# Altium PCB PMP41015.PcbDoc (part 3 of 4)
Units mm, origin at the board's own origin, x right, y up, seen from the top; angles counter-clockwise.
Board outline 173 x 85 mm, 2 copper layers (Top Layer, Bottom Layer), stack 1.575 mm thick; 89 components, 48 nets, 216 pads, 3458 vias.
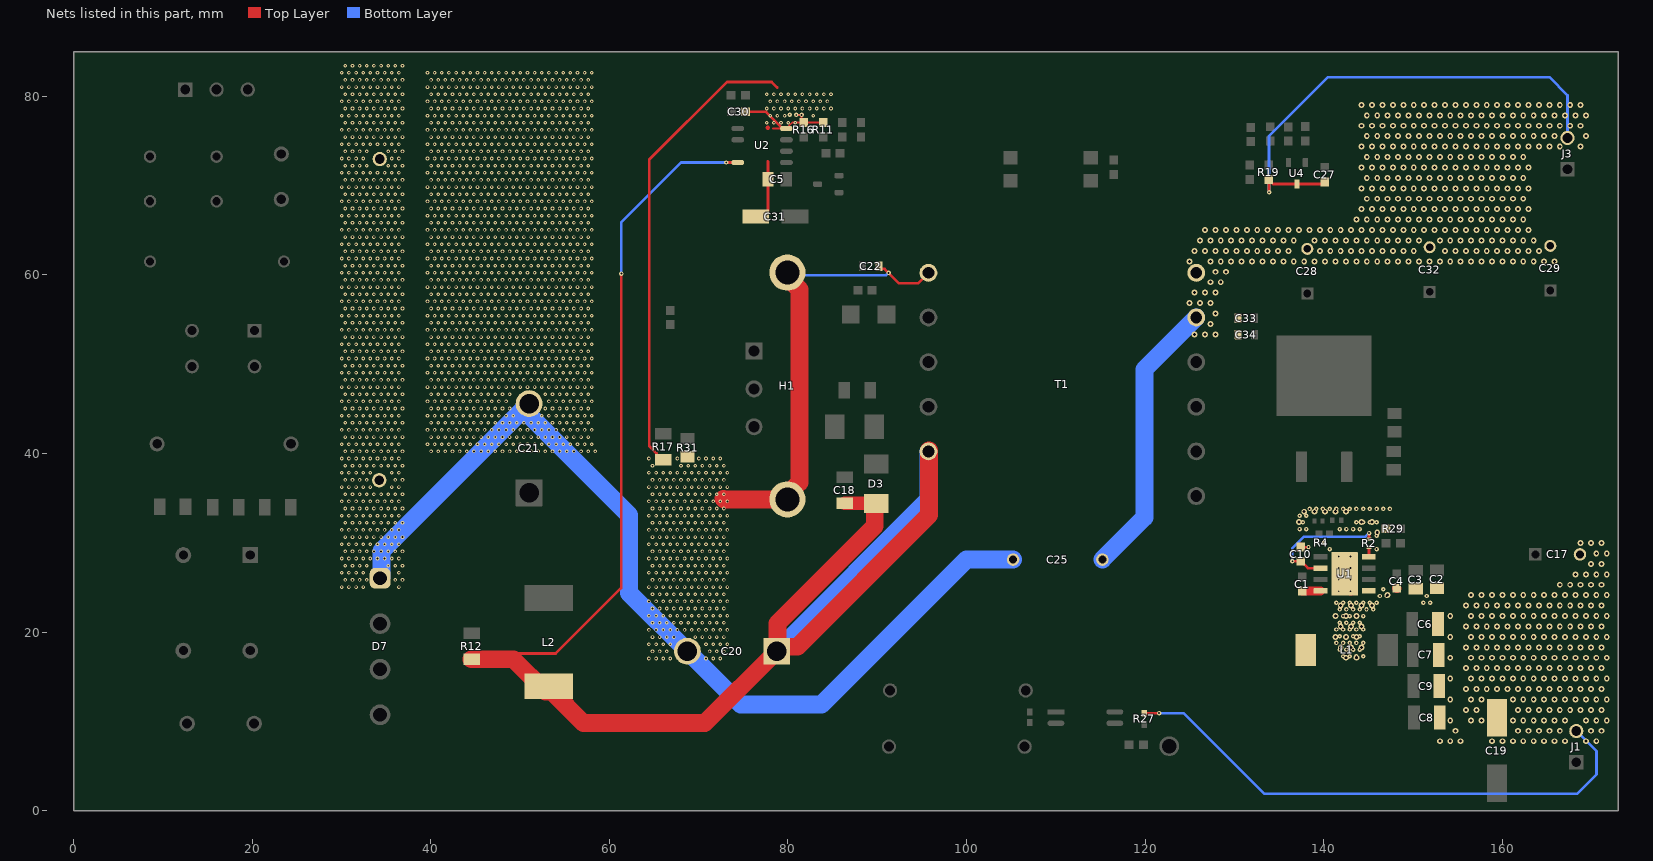
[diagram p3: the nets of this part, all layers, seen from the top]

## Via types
v1: diameter 0.4, hole 0.2, Top Layer to Bottom Layer, 2240 vias
v2: diameter 0.66, hole 0.33, Top Layer to Bottom Layer, 1066 vias
v3: diameter 0.5, hole 0.2, Top Layer to Bottom Layer, 105 vias
v4: diameter 0.67, hole 0.33, Top Layer to Bottom Layer, tented both sides, 41 vias
v5: diameter 0.5, hole 0.2, Top Layer to Bottom Layer, tented both sides, 4 vias
v6: diameter 0.61, hole 0.203, Top Layer to Bottom Layer, tented both sides, 2 vias

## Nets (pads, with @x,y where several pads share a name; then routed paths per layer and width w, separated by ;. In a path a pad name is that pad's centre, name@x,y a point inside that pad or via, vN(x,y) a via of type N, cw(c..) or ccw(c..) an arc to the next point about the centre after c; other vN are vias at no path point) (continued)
PGND: C5.2 C20.2 C21.2 C22.1 C25.1 C30.2 C31.2 D7.1 H1.1 H1.2 pad.1 R11.1 R16.1 R17.1 R31.1 T1.1 U2.4 | length 232
  Top Layer w0.2: 78.338,76.4 79.4,76.4 U2.4@79.825,76.4 80.495,77.07 R16.1@81.754,77.07 ; v3(80.937,77.925) v3(81.521,77.925) ; v3@81.648,78.052 v3(81.521,77.925) ; R16.1@82.08,77.354 R16.1@81.796,77.07 ; R11.1@83.964,77.07 R16.1@81.796,77.07 ; v3(81.521,77.925) 81.521,77.303 R16.1@81.754,77.07 ; R16.1@81.754,77.07 R16.1@81.796,77.07 ; R16.1@81.754,77.07 R16.1@81.775,77.049 R16.1@81.796,77.07
  Top Layer w0.3: R17.1@66.048,39.317 65.773,39.317 65.273,39.817 65.273,40.008 64.463,40.818 64.463,72.907 73.165,81.608 78.181,81.608 78.791,80.999 ; C30.2@75.264,78.27 77.53,78.27 U2.4@79.4,76.4 ; C31.2@76.403,66.541 77.103,66.541 77.758,67.195 C5.2@77.758,70.726 77.758,72.688 77.748,72.698 ; C22.1@90.215,60.96 90.215,60.929 90.465,60.679 90.807,60.679 v3(91.262,60.223) 92.431,59.055 94.554,59.055 T1.1@95.733,60.234
  Top Layer w0.5: 77.748,76.488 77.762,76.503
  Top Layer w2: 72.798,34.929 72.865,34.862 H1.2@79.93,34.862 79.93,35.417 81.28,36.767 81.28,58.357 79.93,59.708 H1.1@79.93,60.262
  Bottom Layer w0.3: H1.2@79.93,34.862 H1.2@79.93,34.878 ; H1.1@79.93,60.262 80.223,59.969 90.986,59.969 91.24,60.223 v3(91.262,60.223)
  Bottom Layer w2: D7.1@34.32,26.033 34.482,26.196 34.482,29.065 C21.2@51.003,45.585 51.003,44.298 62.205,33.096 62.205,24.388 C20.2@68.736,17.856 74.705,11.887 83.769,11.887 100,28.118 C25.1@105.211,28.118
  other v1: 64.423,17.036 65.223,17.036 66.023,17.036 66.823,17.036 70.823,17.036 71.623,17.036 72.423,17.036 64.823,17.836 65.623,17.836 66.423,17.836 71.223,17.836 72.023,17.836 72.823,17.836 64.423,18.636 65.223,18.636 66.023,18.636 66.823,18.636 70.823,18.636 71.623,18.636 72.423,18.636 73.223,18.636 64.823,19.436 65.623,19.436 66.423,19.436 67.223,19.436 69.623,19.436 70.423,19.436 71.223,19.436 72.023,19.436 72.823,19.436 64.423,20.236 65.223,20.236 66.023,20.236 66.823,20.236 67.623,20.236 68.423,20.236 69.223,20.236 70.023,20.236 70.823,20.236 71.623,20.236 72.423,20.236 73.223,20.236 64.823,21.036 65.623,21.036 66.423,21.036 67.223,21.036 68.023,21.036 68.823,21.036 69.623,21.036 70.423,21.036 71.223,21.036 72.023,21.036 72.823,21.036 64.423,21.836 65.223,21.836 66.023,21.836 66.823,21.836 67.623,21.836 68.423,21.836 69.223,21.836 70.023,21.836 70.823,21.836 71.623,21.836 72.423,21.836 73.223,21.836 64.823,22.636 65.623,22.636 66.423,22.636 67.223,22.636 68.023,22.636 68.823,22.636 69.623,22.636 70.423,22.636 71.223,22.636 72.023,22.636 72.823,22.636 64.423,23.436 65.223,23.436 66.023,23.436 66.823,23.436 67.623,23.436 68.423,23.436 69.223,23.436 70.023,23.436 70.823,23.436 71.623,23.436 72.423,23.436 73.223,23.436 64.823,24.236 65.623,24.236 66.423,24.236 67.223,24.236 68.023,24.236 68.823,24.236 69.623,24.236 70.423,24.236 71.223,24.236 72.023,24.236 72.823,24.236 30.023,25.036 30.823,25.036 31.623,25.036 32.423,25.036 36.423,25.036 64.423,25.036 65.223,25.036 66.023,25.036 66.823,25.036 67.623,25.036 68.423,25.036 69.223,25.036 70.023,25.036 70.823,25.036 71.623,25.036 72.423,25.036 73.223,25.036 30.423,25.836 31.223,25.836 32.023,25.836 32.823,25.836 36.023,25.836 36.823,25.836 64.823,25.836 65.623,25.836 66.423,25.836 67.223,25.836 68.023,25.836 68.823,25.836 69.623,25.836 70.423,25.836 71.223,25.836 72.023,25.836 72.823,25.836 30.023,26.636 30.823,26.636 31.623,26.636 32.423,26.636 36.423,26.636 64.423,26.636 65.223,26.636 66.023,26.636 66.823,26.636 67.623,26.636 68.423,26.636 69.223,26.636 70.023,26.636 70.823,26.636 71.623,26.636 72.423,26.636 73.223,26.636 30.423,27.436 31.223,27.436 32.023,27.436 32.823,27.436 35.223,27.436 36.023,27.436 36.823,27.436 64.823,27.436 65.623,27.436 66.423,27.436 67.223,27.436 68.023,27.436 68.823,27.436 69.623,27.436 70.423,27.436 71.223,27.436 72.023,27.436 72.823,27.436 30.023,28.236 30.823,28.236 31.623,28.236 32.423,28.236 33.223,28.236 34.023,28.236 34.823,28.236 35.623,28.236 36.423,28.236 64.423,28.236 65.223,28.236 66.023,28.236 66.823,28.236 67.623,28.236 68.423,28.236 69.223,28.236 70.023,28.236 70.823,28.236 71.623,28.236 72.423,28.236 73.223,28.236 30.423,29.036 31.223,29.036 32.023,29.036 32.823,29.036 33.623,29.036 34.423,29.036 35.223,29.036 36.023,29.036 36.823,29.036 64.823,29.036 65.623,29.036 66.423,29.036 67.223,29.036 68.023,29.036 68.823,29.036 69.623,29.036 70.423,29.036 71.223,29.036 72.023,29.036 72.823,29.036 30.023,29.836 30.823,29.836 31.623,29.836 32.423,29.836 33.223,29.836 34.023,29.836 34.823,29.836 35.623,29.836 36.423,29.836 64.423,29.836 65.223,29.836 66.023,29.836 66.823,29.836 67.623,29.836 68.423,29.836 69.223,29.836 70.023,29.836 70.823,29.836 71.623,29.836 72.423,29.836 73.223,29.836 30.423,30.636 31.223,30.636 32.023,30.636 32.823,30.636 33.623,30.636 34.423,30.636 35.223,30.636 36.023,30.636 36.823,30.636 64.823,30.636 65.623,30.636 66.423,30.636 67.223,30.636 68.023,30.636 68.823,30.636 69.623,30.636 70.423,30.636 71.223,30.636 72.023,30.636 72.823,30.636 30.023,31.436 30.823,31.436 31.623,31.436 32.423,31.436 33.223,31.436 34.023,31.436 34.823,31.436 35.623,31.436 36.423,31.436 64.423,31.436 65.223,31.436 66.023,31.436 66.823,31.436 67.623,31.436 68.423,31.436 69.223,31.436 70.023,31.436 70.823,31.436 71.623,31.436 72.423,31.436 73.223,31.436 30.423,32.236 31.223,32.236 32.023,32.236 32.823,32.236 33.623,32.236 34.423,32.236 35.223,32.236 36.023,32.236 36.823,32.236 64.823,32.236 65.623,32.236 66.423,32.236 67.223,32.236 68.023,32.236 68.823,32.236 69.623,32.236 70.423,32.236 71.223,32.236 72.023,32.236 72.823,32.236 30.023,33.036 30.823,33.036 31.623,33.036 32.423,33.036 33.223,33.036 34.023,33.036 34.823,33.036 35.623,33.036 36.423,33.036 64.423,33.036 65.223,33.036 66.023,33.036 66.823,33.036 67.623,33.036 68.423,33.036 69.223,33.036 70.023,33.036 70.823,33.036 71.623,33.036 72.423,33.036 73.223,33.036 30.423,33.836 31.223,33.836 32.023,33.836 32.823,33.836 33.623,33.836 34.423,33.836 35.223,33.836 36.023,33.836 36.823,33.836 64.823,33.836 65.623,33.836 66.423,33.836 67.223,33.836 68.023,33.836 68.823,33.836 69.623,33.836 70.423,33.836 71.223,33.836 72.023,33.836 72.823,33.836 30.023,34.636 30.823,34.636 31.623,34.636 32.423,34.636 33.223,34.636 34.023,34.636 34.823,34.636 35.623,34.636 36.423,34.636 64.423,34.636 65.223,34.636 66.023,34.636 66.823,34.636 67.623,34.636 68.423,34.636 69.223,34.636 70.023,34.636 70.823,34.636 71.623,34.636 72.423,34.636 73.223,34.636 30.423,35.436 31.223,35.436 32.023,35.436 32.823,35.436 33.623,35.436 34.423,35.436 35.223,35.436 36.023,35.436 36.823,35.436 64.823,35.436 65.623,35.436 66.423,35.436 67.223,35.436 68.023,35.436 68.823,35.436 69.623,35.436 70.423,35.436 71.223,35.436 72.023,35.436 72.823,35.436 30.023,36.236 30.823,36.236 31.623,36.236 32.423,36.236 33.223,36.236 35.623,36.236 36.423,36.236 64.423,36.236 65.223,36.236 66.023,36.236 66.823,36.236 67.623,36.236 68.423,36.236 69.223,36.236 70.023,36.236 70.823,36.236 71.623,36.236 72.423,36.236 73.223,36.236 30.423,37.036 31.223,37.036 32.023,37.036 32.823,37.036 36.023,37.036 36.823,37.036 64.823,37.036 65.623,37.036 66.423,37.036 67.223,37.036 68.023,37.036 68.823,37.036 69.623,37.036 70.423,37.036 71.223,37.036 72.023,37.036 72.823,37.036 30.023,37.836 30.823,37.836 31.623,37.836 32.423,37.836 33.223,37.836 35.623,37.836 36.423,37.836 64.423,37.836 65.223,37.836 66.023,37.836 66.823,37.836 67.623,37.836 68.423,37.836 69.223,37.836 70.023,37.836 70.823,37.836 71.623,37.836 72.423,37.836 73.223,37.836 30.423,38.636 31.223,38.636 32.023,38.636 32.823,38.636 33.623,38.636 34.423,38.636 35.223,38.636 36.023,38.636 36.823,38.636 64.823,38.636 68.023,38.636 68.823,38.636 69.623,38.636 70.423,38.636 71.223,38.636 72.023,38.636 72.823,38.636 30.023,39.436 30.823,39.436 31.623,39.436 32.423,39.436 33.223,39.436 34.023,39.436 34.823,39.436 35.623,39.436 36.423,39.436 64.423,39.436 67.623,39.436 70.023,39.436 70.823,39.436 71.623,39.436 72.423,39.436 30.423,40.236 31.223,40.236 32.023,40.236 32.823,40.236 33.623,40.236 34.423,40.236 35.223,40.236 36.023,40.236 36.823,40.236 40.023,40.236 40.823,40.236 41.623,40.236 42.423,40.236 43.223,40.236 44.023,40.236 44.823,40.236 45.623,40.236 46.423,40.236 47.223,40.236 48.023,40.236 48.823,40.236 49.623,40.236 50.423,40.236 51.223,40.236 52.023,40.236 52.823,40.236 53.623,40.236 54.423,40.236 55.223,40.236 56.023,40.236 56.823,40.236 57.623,40.236 58.423,40.236 30.023,41.036 30.823,41.036 31.623,41.036 32.423,41.036 33.223,41.036 34.023,41.036 34.823,41.036 35.623,41.036 36.423,41.036 39.623,41.036 40.423,41.036 41.223,41.036 42.023,41.036 42.823,41.036 43.623,41.036 44.423,41.036 45.223,41.036 46.023,41.036 46.823,41.036 47.623,41.036 48.423,41.036 49.223,41.036 50.023,41.036 50.823,41.036 51.623,41.036 52.423,41.036 53.223,41.036 54.023,41.036 54.823,41.036 55.623,41.036 56.423,41.036 57.223,41.036 58.023,41.036 30.423,41.836 31.223,41.836 32.023,41.836 32.823,41.836 33.623,41.836 34.423,41.836 35.223,41.836 36.023,41.836 36.823,41.836 40.023,41.836 40.823,41.836 41.623,41.836 42.423,41.836 43.223,41.836 44.023,41.836 44.823,41.836 45.623,41.836 46.423,41.836 47.223,41.836 48.023,41.836 48.823,41.836 49.623,41.836 50.423,41.836 51.223,41.836 52.023,41.836 52.823,41.836 53.623,41.836 54.423,41.836 55.223,41.836 56.023,41.836 56.823,41.836 57.623,41.836 30.023,42.636 30.823,42.636 31.623,42.636 32.423,42.636 33.223,42.636 34.023,42.636 34.823,42.636 35.623,42.636 36.423,42.636 39.623,42.636 40.423,42.636 41.223,42.636 42.023,42.636 42.823,42.636 43.623,42.636 44.423,42.636 45.223,42.636 46.023,42.636 46.823,42.636 47.623,42.636 48.423,42.636 49.223,42.636 50.023,42.636 50.823,42.636 51.623,42.636 52.423,42.636 53.223,42.636 54.023,42.636 54.823,42.636 55.623,42.636 56.423,42.636 57.223,42.636 58.023,42.636 30.423,43.436 31.223,43.436 32.023,43.436 32.823,43.436 33.623,43.436 34.423,43.436 35.223,43.436 36.023,43.436 36.823,43.436 40.023,43.436 40.823,43.436 41.623,43.436 42.423,43.436 43.223,43.436 44.023,43.436 44.823,43.436 45.623,43.436 46.423,43.436 47.223,43.436 48.023,43.436 48.823,43.436 49.623,43.436 50.423,43.436 51.223,43.436 52.023,43.436 52.823,43.436 53.623,43.436 54.423,43.436 55.223,43.436 56.023,43.436 56.823,43.436 57.623,43.436 30.023,44.236 30.823,44.236 31.623,44.236 32.423,44.236 33.223,44.236 34.023,44.236 34.823,44.236 35.623,44.236 36.423,44.236 39.623,44.236 40.423,44.236 41.223,44.236 42.023,44.236 42.823,44.236 43.623,44.236 44.423,44.236 45.223,44.236 46.023,44.236 46.823,44.236 47.623,44.236 48.423,44.236 49.223,44.236 52.423,44.236 53.223,44.236 54.023,44.236 54.823,44.236 55.623,44.236 56.423,44.236 57.223,44.236 58.023,44.236 30.423,45.036 31.223,45.036 32.023,45.036 32.823,45.036 33.623,45.036 34.423,45.036 35.223,45.036 36.023,45.036 36.823,45.036 40.023,45.036 40.823,45.036 41.623,45.036 42.423,45.036 43.223,45.036 44.023,45.036 44.823,45.036 45.623,45.036 46.423,45.036 47.223,45.036 48.023,45.036 48.823,45.036 52.823,45.036 53.623,45.036 54.423,45.036 55.223,45.036 56.023,45.036 56.823,45.036 57.623,45.036 30.023,45.836 30.823,45.836 31.623,45.836 32.423,45.836 33.223,45.836 34.023,45.836 34.823,45.836 35.623,45.836 36.423,45.836 39.623,45.836 40.423,45.836 41.223,45.836 42.023,45.836 42.823,45.836 43.623,45.836 44.423,45.836 45.223,45.836 46.023,45.836 46.823,45.836 47.623,45.836 48.423,45.836 53.223,45.836 54.023,45.836 54.823,45.836 55.623,45.836 56.423,45.836 57.223,45.836 58.023,45.836 30.423,46.637 31.223,46.637 32.023,46.637 32.823,46.637 33.623,46.637 34.423,46.637 35.223,46.637 36.023,46.637 36.823,46.637 40.023,46.637 40.823,46.637 41.623,46.637 42.423,46.637 43.223,46.637 44.023,46.637 44.823,46.637 45.623,46.637 46.423,46.637 47.223,46.637 48.023,46.637 48.823,46.637 52.823,46.637 53.623,46.637 54.423,46.637 55.223,46.637 56.023,46.637 56.823,46.637 57.623,46.637 30.023,47.437 30.823,47.437 31.623,47.437 32.423,47.437 33.223,47.437 34.023,47.437 34.823,47.437 35.623,47.437 36.423,47.437 39.623,47.437 40.423,47.437 41.223,47.437 42.023,47.437 42.823,47.437 43.623,47.437 44.423,47.437 45.223,47.437 46.023,47.437 46.823,47.437 47.623,47.437 48.423,47.437 49.223,47.437 50.023,47.437 50.823,47.437 51.623,47.437 52.423,47.437 53.223,47.437 54.023,47.437 54.823,47.437 55.623,47.437 56.423,47.437 57.223,47.437 58.023,47.437 30.423,48.237 31.223,48.237 32.023,48.237 32.823,48.237 33.623,48.237 34.423,48.237 35.223,48.237 36.023,48.237 36.823,48.237 40.023,48.237 40.823,48.237 41.623,48.237 42.423,48.237 43.223,48.237 44.023,48.237 44.823,48.237 45.623,48.237 46.423,48.237 47.223,48.237 48.023,48.237 48.823,48.237 49.623,48.237 50.423,48.237 51.223,48.237 52.023,48.237 52.823,48.237 53.623,48.237 54.423,48.237 55.223,48.237 56.023,48.237 56.823,48.237 57.623,48.237 30.023,49.037 30.823,49.037 31.623,49.037 32.423,49.037 33.223,49.037 34.023,49.037 34.823,49.037 35.623,49.037 36.423,49.037 39.623,49.037 40.423,49.037 41.223,49.037 42.023,49.037 42.823,49.037 43.623,49.037 44.423,49.037 45.223,49.037 46.023,49.037 46.823,49.037 47.623,49.037 48.423,49.037 49.223,49.037 50.023,49.037 50.823,49.037 51.623,49.037 52.423,49.037 53.223,49.037 54.023,49.037 54.823,49.037 55.623,49.037 56.423,49.037 57.223,49.037 58.023,49.037 30.423,49.837 31.223,49.837 32.023,49.837 32.823,49.837 33.623,49.837 34.423,49.837 35.223,49.837 36.023,49.837 36.823,49.837 40.023,49.837 40.823,49.837 41.623,49.837 42.423,49.837 43.223,49.837 44.023,49.837 44.823,49.837 45.623,49.837 46.423,49.837 47.223,49.837 48.023,49.837 48.823,49.837 49.623,49.837 50.423,49.837 51.223,49.837 52.023,49.837 52.823,49.837 53.623,49.837 54.423,49.837 55.223,49.837 56.023,49.837 56.823,49.837 57.623,49.837 30.023,50.637 30.823,50.637 31.623,50.637 32.423,50.637 33.223,50.637 34.023,50.637 34.823,50.637 35.623,50.637 36.423,50.637 39.623,50.637 40.423,50.637 41.223,50.637 42.023,50.637 42.823,50.637 43.623,50.637 44.423,50.637 45.223,50.637 46.023,50.637 46.823,50.637 47.623,50.637 48.423,50.637 49.223,50.637 50.023,50.637 50.823,50.637 51.623,50.637 52.423,50.637 53.223,50.637 54.023,50.637 54.823,50.637 55.623,50.637 56.423,50.637 57.223,50.637 58.023,50.637 30.423,51.437 31.223,51.437 32.023,51.437 32.823,51.437 33.623,51.437 34.423,51.437 35.223,51.437 36.023,51.437 36.823,51.437 40.023,51.437 40.823,51.437 41.623,51.437 42.423,51.437 43.223,51.437 44.023,51.437 44.823,51.437 45.623,51.437 46.423,51.437 47.223,51.437 48.023,51.437 48.823,51.437 49.623,51.437 50.423,51.437 51.223,51.437 52.023,51.437 52.823,51.437 53.623,51.437 54.423,51.437 55.223,51.437 56.023,51.437 56.823,51.437 57.623,51.437 30.023,52.237 30.823,52.237 31.623,52.237 32.423,52.237 33.223,52.237 34.023,52.237 34.823,52.237 35.623,52.237 36.423,52.237 39.623,52.237 40.423,52.237 41.223,52.237 42.023,52.237 42.823,52.237 43.623,52.237 44.423,52.237 45.223,52.237 46.023,52.237 46.823,52.237 47.623,52.237 48.423,52.237 49.223,52.237 50.023,52.237 50.823,52.237 51.623,52.237 52.423,52.237 53.223,52.237 54.023,52.237 54.823,52.237 55.623,52.237 56.423,52.237 57.223,52.237 58.023,52.237 30.423,53.037 31.223,53.037 32.023,53.037 32.823,53.037 33.623,53.037 34.423,53.037 35.223,53.037 36.023,53.037 36.823,53.037 40.023,53.037 40.823,53.037 41.623,53.037 42.423,53.037 43.223,53.037 44.023,53.037 44.823,53.037 45.623,53.037 46.423,53.037 47.223,53.037 48.023,53.037 48.823,53.037 49.623,53.037 50.423,53.037 51.223,53.037 52.023,53.037 52.823,53.037 53.623,53.037 54.423,53.037 55.223,53.037 56.023,53.037 56.823,53.037 57.623,53.037 30.023,53.837 30.823,53.837 31.623,53.837 32.423,53.837 33.223,53.837 34.023,53.837 34.823,53.837 35.623,53.837 36.423,53.837 39.623,53.837 40.423,53.837 41.223,53.837 42.023,53.837 42.823,53.837 43.623,53.837 44.423,53.837 45.223,53.837 46.023,53.837 46.823,53.837 47.623,53.837 48.423,53.837 49.223,53.837 50.023,53.837 50.823,53.837 51.623,53.837 52.423,53.837 53.223,53.837 54.023,53.837 54.823,53.837 55.623,53.837 56.423,53.837 57.223,53.837 58.023,53.837 30.423,54.637 31.223,54.637 32.023,54.637 32.823,54.637 33.623,54.637 34.423,54.637 35.223,54.637 36.023,54.637 36.823,54.637 40.023,54.637 40.823,54.637 41.623,54.637 42.423,54.637 43.223,54.637 44.023,54.637 44.823,54.637 45.623,54.637 46.423,54.637 47.223,54.637 48.023,54.637 48.823,54.637 49.623,54.637 50.423,54.637 51.223,54.637 52.023,54.637 52.823,54.637 53.623,54.637 54.423,54.637 55.223,54.637 56.023,54.637 56.823,54.637 57.623,54.637 30.023,55.437 30.823,55.437 31.623,55.437 32.423,55.437 33.223,55.437 34.023,55.437 34.823,55.437 35.623,55.437 36.423,55.437 39.623,55.437 40.423,55.437 41.223,55.437 42.023,55.437 42.823,55.437 43.623,55.437 44.423,55.437 45.223,55.437 46.023,55.437 46.823,55.437 47.623,55.437 48.423,55.437 49.223,55.437 50.023,55.437 50.823,55.437 51.623,55.437 52.423,55.437 53.223,55.437 54.023,55.437 54.823,55.437 55.623,55.437 56.423,55.437 57.223,55.437 58.023,55.437 30.423,56.237 31.223,56.237 32.023,56.237 32.823,56.237 33.623,56.237 34.423,56.237 35.223,56.237 36.023,56.237 36.823,56.237 40.023,56.237 40.823,56.237 41.623,56.237 42.423,56.237 43.223,56.237 44.023,56.237 44.823,56.237 45.623,56.237 46.423,56.237 47.223,56.237 48.023,56.237 48.823,56.237 49.623,56.237 50.423,56.237 51.223,56.237 52.023,56.237 52.823,56.237 53.623,56.237 54.423,56.237 55.223,56.237 56.023,56.237 56.823,56.237 57.623,56.237 30.023,57.037 30.823,57.037 31.623,57.037 32.423,57.037 33.223,57.037 34.023,57.037 34.823,57.037 35.623,57.037 36.423,57.037 39.623,57.037 40.423,57.037 41.223,57.037 42.023,57.037 42.823,57.037 43.623,57.037 44.423,57.037 45.223,57.037 46.023,57.037 46.823,57.037 47.623,57.037 48.423,57.037 49.223,57.037 50.023,57.037 50.823,57.037 51.623,57.037 52.423,57.037 53.223,57.037 54.023,57.037 54.823,57.037 55.623,57.037 56.423,57.037 57.223,57.037 58.023,57.037 30.423,57.837 31.223,57.837 32.023,57.837 32.823,57.837 33.623,57.837 34.423,57.837 35.223,57.837 36.023,57.837 36.823,57.837 40.023,57.837 40.823,57.837 41.623,57.837 42.423,57.837 43.223,57.837 44.023,57.837 44.823,57.837 45.623,57.837 46.423,57.837 47.223,57.837 48.023,57.837 48.823,57.837 49.623,57.837 50.423,57.837 51.223,57.837 52.023,57.837 52.823,57.837 53.623,57.837 54.423,57.837 55.223,57.837 56.023,57.837 56.823,57.837 57.623,57.837 30.023,58.637 30.823,58.637 31.623,58.637 32.423,58.637 33.223,58.637 34.023,58.637 34.823,58.637 35.623,58.637 36.423,58.637 39.623,58.637 40.423,58.637 41.223,58.637 42.023,58.637 42.823,58.637 43.623,58.637 44.423,58.637 45.223,58.637 46.023,58.637 46.823,58.637 47.623,58.637 48.423,58.637 49.223,58.637 50.023,58.637 50.823,58.637 51.623,58.637 52.423,58.637 53.223,58.637 54.023,58.637 54.823,58.637 55.623,58.637 56.423,58.637 57.223,58.637 58.023,58.637 30.423,59.437 31.223,59.437 32.023,59.437 32.823,59.437 33.623,59.437 34.423,59.437 35.223,59.437 36.023,59.437 36.823,59.437 40.023,59.437 40.823,59.437 41.623,59.437 42.423,59.437 43.223,59.437 44.023,59.437 44.823,59.437 45.623,59.437 46.423,59.437 47.223,59.437 48.023,59.437 48.823,59.437 49.623,59.437 50.423,59.437 51.223,59.437 52.023,59.437 52.823,59.437 53.623,59.437 54.423,59.437 55.223,59.437 56.023,59.437 56.823,59.437 57.623,59.437 30.023,60.237 30.823,60.237 31.623,60.237 32.423,60.237 33.223,60.237 34.023,60.237 34.823,60.237 35.623,60.237 36.423,60.237 39.623,60.237 40.423,60.237 41.223,60.237 42.023,60.237 42.823,60.237 43.623,60.237 44.423,60.237 45.223,60.237 46.023,60.237 46.823,60.237 47.623,60.237 48.423,60.237 49.223,60.237 50.023,60.237 50.823,60.237 51.623,60.237 52.423,60.237 53.223,60.237 54.023,60.237 54.823,60.237 55.623,60.237 56.423,60.237 57.223,60.237 58.023,60.237 30.423,61.037 31.223,61.037 32.023,61.037 32.823,61.037 33.623,61.037 34.423,61.037 35.223,61.037 36.023,61.037 36.823,61.037 40.023,61.037 40.823,61.037 41.623,61.037 42.423,61.037 43.223,61.037 44.023,61.037 44.823,61.037 45.623,61.037 46.423,61.037 47.223,61.037 48.023,61.037 48.823,61.037 49.623,61.037 50.423,61.037 51.223,61.037 52.023,61.037 52.823,61.037 53.623,61.037 54.423,61.037 55.223,61.037 56.023,61.037 56.823,61.037 57.623,61.037 30.023,61.837 30.823,61.837 31.623,61.837 32.423,61.837 33.223,61.837 34.023,61.837 34.823,61.837 35.623,61.837 36.423,61.837 39.623,61.837 40.423,61.837 41.223,61.837 42.023,61.837 42.823,61.837 43.623,61.837 44.423,61.837 45.223,61.837 46.023,61.837 46.823,61.837 47.623,61.837 48.423,61.837 49.223,61.837 50.023,61.837 50.823,61.837 51.623,61.837 52.423,61.837 53.223,61.837 54.023,61.837 54.823,61.837 55.623,61.837 56.423,61.837 57.223,61.837 58.023,61.837 30.423,62.637 31.223,62.637 32.023,62.637 32.823,62.637 33.623,62.637 34.423,62.637 35.223,62.637 36.023,62.637 36.823,62.637 40.023,62.637 40.823,62.637 41.623,62.637 42.423,62.637 43.223,62.637 44.023,62.637 44.823,62.637 45.623,62.637 46.423,62.637 47.223,62.637 48.023,62.637 48.823,62.637 49.623,62.637 50.423,62.637 51.223,62.637 52.023,62.637 52.823,62.637 53.623,62.637 54.423,62.637 55.223,62.637 56.023,62.637 56.823,62.637 57.623,62.637 30.023,63.437 30.823,63.437 31.623,63.437 32.423,63.437 33.223,63.437 34.023,63.437 34.823,63.437 35.623,63.437 36.423,63.437 39.623,63.437 40.423,63.437 41.223,63.437 42.023,63.437 42.823,63.437 43.623,63.437 44.423,63.437 45.223,63.437 46.023,63.437 46.823,63.437 47.623,63.437 48.423,63.437 49.223,63.437 50.023,63.437 50.823,63.437 51.623,63.437 52.423,63.437 53.223,63.437 54.023,63.437 54.823,63.437 55.623,63.437 56.423,63.437 57.223,63.437 58.023,63.437 30.423,64.237 31.223,64.237 32.023,64.237 32.823,64.237 33.623,64.237 34.423,64.237 35.223,64.237 36.023,64.237 36.823,64.237 40.023,64.237 40.823,64.237 41.623,64.237 42.423,64.237 43.223,64.237 44.023,64.237 44.823,64.237 45.623,64.237 46.423,64.237 47.223,64.237 48.023,64.237 48.823,64.237 49.623,64.237 50.423,64.237 51.223,64.237 52.023,64.237 52.823,64.237 53.623,64.237 54.423,64.237 55.223,64.237 56.023,64.237 56.823,64.237 57.623,64.237 30.023,65.037 30.823,65.037 31.623,65.037 32.423,65.037 33.223,65.037 34.023,65.037 34.823,65.037 35.623,65.037 36.423,65.037 39.623,65.037 40.423,65.037 41.223,65.037 42.023,65.037 42.823,65.037 43.623,65.037 44.423,65.037 45.223,65.037 46.023,65.037 46.823,65.037 47.623,65.037 48.423,65.037 49.223,65.037 50.023,65.037 50.823,65.037 51.623,65.037 52.423,65.037 53.223,65.037 54.023,65.037 54.823,65.037 55.623,65.037 56.423,65.037 57.223,65.037 58.023,65.037 30.423,65.837 31.223,65.837 32.023,65.837 32.823,65.837 33.623,65.837 34.423,65.837 35.223,65.837 36.023,65.837 36.823,65.837 40.023,65.837 40.823,65.837 41.623,65.837 42.423,65.837 43.223,65.837 44.023,65.837 44.823,65.837 45.623,65.837 46.423,65.837 47.223,65.837 48.023,65.837 48.823,65.837 49.623,65.837 50.423,65.837 51.223,65.837 52.023,65.837 52.823,65.837 53.623,65.837 54.423,65.837 55.223,65.837 56.023,65.837 56.823,65.837 57.623,65.837 30.023,66.637 30.823,66.637 31.623,66.637 32.423,66.637 33.223,66.637 34.023,66.637 34.823,66.637 35.623,66.637 36.423,66.637 39.623,66.637 40.423,66.637 41.223,66.637 42.023,66.637 42.823,66.637 43.623,66.637 44.423,66.637 45.223,66.637 46.023,66.637 46.823,66.637 47.623,66.637 48.423,66.637 49.223,66.637 50.023,66.637 50.823,66.637 51.623,66.637 52.423,66.637 53.223,66.637 54.023,66.637 54.823,66.637 55.623,66.637 56.423,66.637 57.223,66.637 58.023,66.637 30.423,67.437 31.223,67.437 32.023,67.437 32.823,67.437 33.623,67.437 34.423,67.437 35.223,67.437 36.023,67.437 36.823,67.437 40.023,67.437 40.823,67.437 41.623,67.437 42.423,67.437 43.223,67.437 44.023,67.437 44.823,67.437 45.623,67.437 46.423,67.437 47.223,67.437 48.023,67.437 48.823,67.437 49.623,67.437 50.423,67.437 51.223,67.437 52.023,67.437 52.823,67.437 53.623,67.437 54.423,67.437 55.223,67.437 56.023,67.437 56.823,67.437 57.623,67.437 30.023,68.237 30.823,68.237 31.623,68.237 32.423,68.237 33.223,68.237 34.023,68.237 34.823,68.237 35.623,68.237 36.423,68.237 39.623,68.237 40.423,68.237 41.223,68.237 42.023,68.237 42.823,68.237 43.623,68.237 44.423,68.237 45.223,68.237 46.023,68.237 46.823,68.237 47.623,68.237 48.423,68.237 49.223,68.237 50.023,68.237 50.823,68.237 51.623,68.237 52.423,68.237 53.223,68.237 54.023,68.237 54.823,68.237 55.623,68.237 56.423,68.237 57.223,68.237 58.023,68.237 30.423,69.037 31.223,69.037 32.023,69.037 32.823,69.037 33.623,69.037 34.423,69.037 35.223,69.037 36.023,69.037 36.823,69.037 40.023,69.037 40.823,69.037 41.623,69.037 42.423,69.037 43.223,69.037 44.023,69.037 44.823,69.037 45.623,69.037 46.423,69.037 47.223,69.037 48.023,69.037 48.823,69.037 49.623,69.037 50.423,69.037 51.223,69.037 52.023,69.037 52.823,69.037 53.623,69.037 54.423,69.037 55.223,69.037 56.023,69.037 56.823,69.037 57.623,69.037 30.023,69.837 30.823,69.837 31.623,69.837 32.423,69.837 33.223,69.837 34.023,69.837 34.823,69.837 35.623,69.837 36.423,69.837 39.623,69.837 40.423,69.837 41.223,69.837 42.023,69.837 42.823,69.837 43.623,69.837 44.423,69.837 45.223,69.837 46.023,69.837 46.823,69.837 47.623,69.837 48.423,69.837 49.223,69.837 50.023,69.837 50.823,69.837 51.623,69.837 52.423,69.837 53.223,69.837 54.023,69.837 54.823,69.837 55.623,69.837 56.423,69.837 57.223,69.837 58.023,69.837 30.423,70.637 31.223,70.637 32.023,70.637 32.823,70.637 33.623,70.637 34.423,70.637 35.223,70.637 36.023,70.637 36.823,70.637 40.023,70.637 40.823,70.637 41.623,70.637 42.423,70.637 43.223,70.637 44.023,70.637 44.823,70.637 45.623,70.637 46.423,70.637 47.223,70.637 48.023,70.637 48.823,70.637 49.623,70.637 50.423,70.637 51.223,70.637 52.023,70.637 52.823,70.637 53.623,70.637 54.423,70.637 55.223,70.637 56.023,70.637 56.823,70.637 57.623,70.637 30.023,71.437 30.823,71.437 31.623,71.437 32.423,71.437 33.223,71.437 34.023,71.437 34.823,71.437 35.623,71.437 36.423,71.437 39.623,71.437 40.423,71.437 41.223,71.437 42.023,71.437 42.823,71.437 43.623,71.437 44.423,71.437 45.223,71.437 46.023,71.437 46.823,71.437 47.623,71.437 48.423,71.437 49.223,71.437 50.023,71.437 50.823,71.437 51.623,71.437 52.423,71.437 53.223,71.437 54.023,71.437 54.823,71.437 55.623,71.437 56.423,71.437 57.223,71.437 58.023,71.437 30.423,72.237 31.223,72.237 32.023,72.237 32.823,72.237 35.223,72.237 36.023,72.237 36.823,72.237 40.023,72.237 40.823,72.237 41.623,72.237 42.423,72.237 43.223,72.237 44.023,72.237 44.823,72.237 45.623,72.237 46.423,72.237 47.223,72.237 48.023,72.237 48.823,72.237 49.623,72.237 50.423,72.237 51.223,72.237 52.023,72.237 52.823,72.237 53.623,72.237 54.423,72.237 55.223,72.237 56.023,72.237 56.823,72.237 57.623,72.237 30.023,73.037 30.823,73.037 31.623,73.037 32.423,73.037 35.623,73.037 36.423,73.037 39.623,73.037 40.423,73.037 41.223,73.037 42.023,73.037 42.823,73.037 43.623,73.037 44.423,73.037 45.223,73.037 46.023,73.037 46.823,73.037 47.623,73.037 48.423,73.037 49.223,73.037 50.023,73.037 50.823,73.037 51.623,73.037 52.423,73.037 53.223,73.037 54.023,73.037 54.823,73.037 55.623,73.037 56.423,73.037 57.223,73.037 58.023,73.037 30.423,73.837 31.223,73.837 32.023,73.837 32.823,73.837 35.223,73.837 36.023,73.837 36.823,73.837 40.023,73.837 40.823,73.837 41.623,73.837 42.423,73.837 43.223,73.837 44.023,73.837 44.823,73.837 45.623,73.837 46.423,73.837 47.223,73.837 48.023,73.837 48.823,73.837 49.623,73.837 50.423,73.837 51.223,73.837 52.023,73.837 52.823,73.837 53.623,73.837 54.423,73.837 55.223,73.837 56.023,73.837 56.823,73.837 57.623,73.837 30.023,74.637 30.823,74.637 31.623,74.637 32.423,74.637 33.223,74.637 34.023,74.637 34.823,74.637 35.623,74.637 36.423,74.637 39.623,74.637 40.423,74.637 41.223,74.637 42.023,74.637 42.823,74.637 43.623,74.637 44.423,74.637 45.223,74.637 46.023,74.637 46.823,74.637 47.623,74.637 48.423,74.637 49.223,74.637 50.023,74.637 50.823,74.637 51.623,74.637 52.423,74.637 53.223,74.637 54.023,74.637 54.823,74.637 55.623,74.637 56.423,74.637 57.223,74.637 58.023,74.637 30.423,75.437 31.223,75.437 32.023,75.437 32.823,75.437 33.623,75.437 34.423,75.437 35.223,75.437 36.023,75.437 36.823,75.437 40.023,75.437 40.823,75.437 41.623,75.437 42.423,75.437 43.223,75.437 44.023,75.437 44.823,75.437 45.623,75.437 46.423,75.437 47.223,75.437 48.023,75.437 48.823,75.437 49.623,75.437 50.423,75.437 51.223,75.437 52.023,75.437 52.823,75.437 53.623,75.437 54.423,75.437 55.223,75.437 56.023,75.437 56.823,75.437 57.623,75.437 30.023,76.237 30.823,76.237 31.623,76.237 32.423,76.237 33.223,76.237 34.023,76.237 34.823,76.237 35.623,76.237 36.423,76.237 39.623,76.237 40.423,76.237 41.223,76.237 42.023,76.237 42.823,76.237 43.623,76.237 44.423,76.237 45.223,76.237 46.023,76.237 46.823,76.237 47.623,76.237 48.423,76.237 49.223,76.237 50.023,76.237 50.823,76.237 51.623,76.237 52.423,76.237 53.223,76.237 54.023,76.237 54.823,76.237 55.623,76.237 56.423,76.237 57.223,76.237 58.023,76.237 30.423,77.037 31.223,77.037 32.023,77.037 32.823,77.037 33.623,77.037 34.423,77.037 35.223,77.037 36.023,77.037 36.823,77.037 40.023,77.037 40.823,77.037 41.623,77.037 42.423,77.037 43.223,77.037 44.023,77.037 44.823,77.037 45.623,77.037 46.423,77.037 47.223,77.037 48.023,77.037 48.823,77.037 49.623,77.037 50.423,77.037 51.223,77.037 52.023,77.037 52.823,77.037 53.623,77.037 54.423,77.037 55.223,77.037 56.023,77.037 56.823,77.037 57.623,77.037 77.623,77.037 78.423,77.037 79.223,77.037 80.023,77.037 80.823,77.037 30.023,77.837 30.823,77.837 31.623,77.837 32.423,77.837 33.223,77.837 34.023,77.837 34.823,77.837 35.623,77.837 36.423,77.837 39.623,77.837 40.423,77.837 41.223,77.837 42.023,77.837 42.823,77.837 43.623,77.837 44.423,77.837 45.223,77.837 46.023,77.837 46.823,77.837 47.623,77.837 48.423,77.837 49.223,77.837 50.023,77.837 50.823,77.837 51.623,77.837 52.423,77.837 53.223,77.837 54.023,77.837 54.823,77.837 55.623,77.837 56.423,77.837 57.223,77.837 58.023,77.837 78.023,77.837 78.823,77.837 79.623,77.837 82.823,77.837 30.423,78.637 31.223,78.637 32.023,78.637 32.823,78.637 33.623,78.637 34.423,78.637 35.223,78.637 36.023,78.637 36.823,78.637 40.023,78.637 40.823,78.637 41.623,78.637 42.423,78.637 43.223,78.637 44.023,78.637 44.823,78.637 45.623,78.637 46.423,78.637 47.223,78.637 48.023,78.637 48.823,78.637 49.623,78.637 50.423,78.637 51.223,78.637 52.023,78.637 52.823,78.637 53.623,78.637 54.423,78.637 55.223,78.637 56.023,78.637 56.823,78.637 57.623,78.637 77.623,78.637 78.423,78.637 79.223,78.637 80.023,78.637 80.823,78.637 81.623,78.637 82.423,78.637 83.223,78.637 84.023,78.637 84.823,78.637 30.023,79.437 30.823,79.437 31.623,79.437 32.423,79.437 33.223,79.437 34.023,79.437 34.823,79.437 35.623,79.437 36.423,79.437 39.623,79.437 40.423,79.437 41.223,79.437 42.023,79.437 42.823,79.437 43.623,79.437 44.423,79.437 45.223,79.437 46.023,79.437 46.823,79.437 47.623,79.437 48.423,79.437 49.223,79.437 50.023,79.437 50.823,79.437 51.623,79.437 52.423,79.437 53.223,79.437 54.023,79.437 54.823,79.437 55.623,79.437 56.423,79.437 57.223,79.437 58.023,79.437 78.023,79.437 78.823,79.437 79.623,79.437 80.423,79.437 81.223,79.437 82.023,79.437 82.823,79.437 83.623,79.437 84.423,79.437 30.423,80.237 31.223,80.237 32.023,80.237 32.823,80.237 33.623,80.237 34.423,80.237 35.223,80.237 36.023,80.237 36.823,80.237 40.023,80.237 40.823,80.237 41.623,80.237 42.423,80.237 43.223,80.237 44.023,80.237 44.823,80.237 45.623,80.237 46.423,80.237 47.223,80.237 48.023,80.237 48.823,80.237 49.623,80.237 50.423,80.237 51.223,80.237 52.023,80.237 52.823,80.237 53.623,80.237 54.423,80.237 55.223,80.237 56.023,80.237 56.823,80.237 57.623,80.237 77.623,80.237 78.423,80.237 79.223,80.237 80.023,80.237 80.823,80.237 81.623,80.237 82.423,80.237 83.223,80.237 84.023,80.237 84.823,80.237 30.023,81.037 30.823,81.037 31.623,81.037 32.423,81.037 33.223,81.037 34.023,81.037 34.823,81.037 35.623,81.037 36.423,81.037 39.623,81.037 40.423,81.037 41.223,81.037 42.023,81.037 42.823,81.037 43.623,81.037 44.423,81.037 45.223,81.037 46.023,81.037 46.823,81.037 47.623,81.037 48.423,81.037 49.223,81.037 50.023,81.037 50.823,81.037 51.623,81.037 52.423,81.037 53.223,81.037 54.023,81.037 54.823,81.037 55.623,81.037 56.423,81.037 57.223,81.037 58.023,81.037 30.423,81.837 31.223,81.837 32.023,81.837 32.823,81.837 33.623,81.837 34.423,81.837 35.223,81.837 36.023,81.837 36.823,81.837 40.023,81.837 40.823,81.837 41.623,81.837 42.423,81.837 43.223,81.837 44.023,81.837 44.823,81.837 45.623,81.837 46.423,81.837 47.223,81.837 48.023,81.837 48.823,81.837 49.623,81.837 50.423,81.837 51.223,81.837 52.023,81.837 52.823,81.837 53.623,81.837 54.423,81.837 55.223,81.837 56.023,81.837 56.823,81.837 57.623,81.837 30.023,82.637 30.823,82.637 31.623,82.637 32.423,82.637 33.223,82.637 34.023,82.637 34.823,82.637 35.623,82.637 36.423,82.637 39.623,82.637 40.423,82.637 41.223,82.637 42.023,82.637 42.823,82.637 43.623,82.637 44.423,82.637 45.223,82.637 46.023,82.637 46.823,82.637 47.623,82.637 48.423,82.637 49.223,82.637 50.023,82.637 50.823,82.637 51.623,82.637 52.423,82.637 53.223,82.637 54.023,82.637 54.823,82.637 55.623,82.637 56.423,82.637 57.223,82.637 58.023,82.637 30.423,83.437 31.223,83.437 32.023,83.437 32.823,83.437 33.623,83.437 34.423,83.437 35.223,83.437 36.023,83.437 36.823,83.437
  other v3: 80.2,77.95
PGOOD: R2.1 U1.4 | length 1.1
  Top Layer w0.3: U1.4@145.048,28.423 145.085,28.459 R2.1@145.085,29.497
SGND: C2.2 C3.2 C4.2 C6.2 C7.2 C8.2 C9.2 C10.2 C17.2 C19.2 C25.2 C27.2 C28.2 C29.2 C32.2 C33.1 C34.1 J1.2 J3.2 R4.1 R19.1 R27.1 R29.1 T1.11 T1.12 U1.1 U1.9 U4.3 | length 151.4
  Top Layer w0.2: U1.9@142.348,26.518 U1.9@142.348,28.061
  Top Layer w0.3: R27.1@119.893,10.862 119.954,10.922 v3(121.564,10.922) ; R19.1@133.833,70.688 R19.1@133.883,70.638 ; v3(133.883,69.253) R19.1@133.883,70.638 ; C10.2@137.446,29.53 137.46,29.515 v3(138.303,29.515) ; C10.2@137.446,29.833 C10.2@137.446,29.856 ; C27.2@140.106,70.409 139.875,70.178 U4.3@137.008,70.178 134.343,70.178 R19.1@133.883,70.638 ; U1.9@142.348,28.061 U1.9@142.348,28.289
  Top Layer w1: v5(142.998,24.568) U1.9@143.043,24.613 ; C4.2@148.178,24.902 C4.2@148.214,24.867 ; C2.2@152.678,24.867 C2.2@152.704,24.892
  Bottom Layer w0.3: v3(121.564,10.922) 124.308,10.922 133.35,1.88 168.377,1.88 170.561,4.064 170.561,6.652 J1.2@168.3,8.913 ; v3(133.883,69.253) 133.883,75.565 140.462,82.144 165.278,82.144 167.307,80.114 J3.2@167.307,75.344
  Bottom Layer w2: C25.2@115.211,28.118 119.913,32.821 119.913,49.414 T1.11@125.733,55.234
  other v2: 153.01,7.772 154.178,7.772 155.346,7.772 158.852,7.772 160.02,7.772 161.188,7.772 162.357,7.772 163.525,7.772 164.694,7.772 165.862,7.772 167.03,7.772 169.367,7.772 170.536,7.772 154.762,8.941 161.773,8.941 162.941,8.941 164.109,8.941 165.278,8.941 166.446,8.941 169.951,8.941 171.12,8.941 154.178,10.109 156.515,10.109 157.683,10.109 161.188,10.109 162.357,10.109 163.525,10.109 164.694,10.109 165.862,10.109 167.03,10.109 169.367,10.109 170.536,10.109 171.704,10.109 155.931,11.278 157.099,11.278 161.773,11.278 162.941,11.278 164.109,11.278 165.278,11.278 166.446,11.278 167.615,11.278 168.783,11.278 169.951,11.278 171.12,11.278 154.178,12.446 156.515,12.446 157.683,12.446 161.188,12.446 162.357,12.446 163.525,12.446 164.694,12.446 165.862,12.446 167.03,12.446 168.199,12.446 169.367,12.446 170.536,12.446 171.704,12.446 155.931,13.614 157.099,13.614 158.267,13.614 159.436,13.614 160.604,13.614 161.773,13.614 162.941,13.614 164.109,13.614 165.278,13.614 166.446,13.614 167.615,13.614 168.783,13.614 169.951,13.614 171.12,13.614 154.178,14.783 156.515,14.783 157.683,14.783 158.852,14.783 160.02,14.783 161.188,14.783 162.357,14.783 163.525,14.783 164.694,14.783 165.862,14.783 167.03,14.783 168.199,14.783 169.367,14.783 170.536,14.783 171.704,14.783 155.931,15.951 157.099,15.951 158.267,15.951 159.436,15.951 160.604,15.951 161.773,15.951 162.941,15.951 164.109,15.951 165.278,15.951 166.446,15.951 167.615,15.951 168.783,15.951 169.951,15.951 171.12,15.951 142.494,17.12 143.662,17.12 154.178,17.12 156.515,17.12 157.683,17.12 158.852,17.12 160.02,17.12 161.188,17.12 162.357,17.12 163.525,17.12 164.694,17.12 165.862,17.12 167.03,17.12 168.199,17.12 169.367,17.12 170.536,17.12 171.704,17.12 141.91,18.288 143.078,18.288 144.247,18.288 155.931,18.288 157.099,18.288 158.267,18.288 159.436,18.288 160.604,18.288 161.773,18.288 162.941,18.288 164.109,18.288 165.278,18.288 166.446,18.288 167.615,18.288 168.783,18.288 169.951,18.288 171.12,18.288 141.326,19.456 142.494,19.456 143.662,19.456 154.178,19.456 156.515,19.456 157.683,19.456 158.852,19.456 160.02,19.456 161.188,19.456 162.357,19.456 163.525,19.456 164.694,19.456 165.862,19.456 167.03,19.456 168.199,19.456 169.367,19.456 170.536,19.456 171.704,19.456 141.91,20.625 143.078,20.625 144.247,20.625 155.931,20.625 157.099,20.625 158.267,20.625 159.436,20.625 160.604,20.625 161.773,20.625 162.941,20.625 164.109,20.625 165.278,20.625 166.446,20.625 167.615,20.625 168.783,20.625 169.951,20.625 171.12,20.625 141.326,21.793 142.494,21.793 143.662,21.793 154.178,21.793 156.515,21.793 157.683,21.793 158.852,21.793 160.02,21.793 161.188,21.793 162.357,21.793 163.525,21.793 164.694,21.793 165.862,21.793 167.03,21.793 168.199,21.793 169.367,21.793 170.536,21.793 171.704,21.793 141.91,22.962 143.078,22.962 144.247,22.962 145.415,22.962 155.931,22.962 157.099,22.962 158.267,22.962 159.436,22.962 160.604,22.962 161.773,22.962 162.941,22.962 164.109,22.962 165.278,22.962 166.446,22.962 167.615,22.962 168.783,22.962 169.951,22.962 171.12,22.962 147.168,24.13 156.515,24.13 157.683,24.13 158.852,24.13 160.02,24.13 161.188,24.13 162.357,24.13 163.525,24.13 164.694,24.13 165.862,24.13 167.03,24.13 168.199,24.13 169.367,24.13 170.536,24.13 171.704,24.13 166.446,25.298 167.615,25.298 168.783,25.298 169.951,25.298 171.12,25.298 168.199,26.467 169.367,26.467 170.536,26.467 171.704,26.467 169.951,27.635 171.12,27.635 170.536,28.804 171.704,28.804 168.783,29.972 169.951,29.972 171.12,29.972 145.999,31.14 137.236,32.309 144.247,32.309 145.415,32.309 137.82,33.477 138.989,33.477 140.157,33.477 141.326,33.477 142.494,33.477 125.552,53.34 126.721,53.34 127.889,53.34 127.305,54.508 127.889,55.677 124.968,56.845 126.136,56.845 127.305,56.845 125.552,58.014 126.721,58.014 127.889,58.014 127.305,59.182 128.473,59.182 127.889,60.35 129.057,60.35 124.968,61.519 127.305,61.519 128.473,61.519 129.642,61.519 130.81,61.519 131.978,61.519 133.147,61.519 134.315,61.519 135.484,61.519 136.652,61.519 137.82,61.519 138.989,61.519 140.157,61.519 141.326,61.519 142.494,61.519 143.662,61.519 144.831,61.519 145.999,61.519 147.168,61.519 148.336,61.519 149.504,61.519 150.673,61.519 151.841,61.519 153.01,61.519 154.178,61.519 155.346,61.519 156.515,61.519 157.683,61.519 158.852,61.519 160.02,61.519 161.188,61.519 162.357,61.519 163.525,61.519 164.694,61.519 165.862,61.519 125.552,62.687 126.721,62.687 127.889,62.687 129.057,62.687 130.226,62.687 131.394,62.687 132.563,62.687 133.731,62.687 134.899,62.687 136.068,62.687 139.573,62.687 140.741,62.687 141.91,62.687 143.078,62.687 144.247,62.687 145.415,62.687 146.583,62.687 147.752,62.687 148.92,62.687 150.089,62.687 153.594,62.687 154.762,62.687 155.931,62.687 157.099,62.687 158.267,62.687 159.436,62.687 160.604,62.687 161.773,62.687 162.941,62.687 164.109,62.687 126.136,63.856 127.305,63.856 128.473,63.856 129.642,63.856 130.81,63.856 131.978,63.856 133.147,63.856 134.315,63.856 135.484,63.856 136.652,63.856 138.989,63.856 140.157,63.856 141.326,63.856 142.494,63.856 143.662,63.856 144.831,63.856 145.999,63.856 147.168,63.856 148.336,63.856 149.504,63.856 150.673,63.856 153.01,63.856 154.178,63.856 155.346,63.856 156.515,63.856 157.683,63.856 158.852,63.856 160.02,63.856 161.188,63.856 162.357,63.856 163.525,63.856 126.721,65.024 127.889,65.024 129.057,65.024 130.226,65.024 131.394,65.024 132.563,65.024 133.731,65.024 134.899,65.024 136.068,65.024 137.236,65.024 138.405,65.024 139.573,65.024 140.741,65.024 141.91,65.024 143.078,65.024 144.247,65.024 145.415,65.024 146.583,65.024 147.752,65.024 148.92,65.024 150.089,65.024 151.257,65.024 152.425,65.024 153.594,65.024 154.762,65.024 155.931,65.024 157.099,65.024 158.267,65.024 159.436,65.024 160.604,65.024 161.773,65.024 162.941,65.024 143.662,66.192 144.831,66.192 145.999,66.192 147.168,66.192 148.336,66.192 149.504,66.192 150.673,66.192 151.841,66.192 153.01,66.192 154.178,66.192 155.346,66.192 156.515,66.192 157.683,66.192 158.852,66.192 160.02,66.192 161.188,66.192 162.357,66.192 144.247,67.361 145.415,67.361 146.583,67.361 147.752,67.361 148.92,67.361 150.089,67.361 151.257,67.361 152.425,67.361 153.594,67.361 154.762,67.361 155.931,67.361 157.099,67.361 158.267,67.361 159.436,67.361 160.604,67.361 161.773,67.361 162.941,67.361 144.831,68.529 145.999,68.529 147.168,68.529 148.336,68.529 149.504,68.529 150.673,68.529 151.841,68.529 153.01,68.529 154.178,68.529 155.346,68.529 156.515,68.529 157.683,68.529 158.852,68.529 160.02,68.529 161.188,68.529 162.357,68.529 144.247,69.698 145.415,69.698 146.583,69.698 147.752,69.698 148.92,69.698 150.089,69.698 151.257,69.698 152.425,69.698 153.594,69.698 154.762,69.698 155.931,69.698 157.099,69.698 158.267,69.698 159.436,69.698 160.604,69.698 161.773,69.698 162.941,69.698 144.831,70.866 145.999,70.866 147.168,70.866 148.336,70.866 149.504,70.866 150.673,70.866 151.841,70.866 153.01,70.866 154.178,70.866 155.346,70.866 156.515,70.866 157.683,70.866 158.852,70.866 160.02,70.866 161.188,70.866 162.357,70.866 144.247,72.034 145.415,72.034 146.583,72.034 147.752,72.034 148.92,72.034 150.089,72.034 151.257,72.034 152.425,72.034 153.594,72.034 154.762,72.034 155.931,72.034 157.099,72.034 158.267,72.034 159.436,72.034 160.604,72.034 161.773,72.034 162.941,72.034 144.831,73.203 145.999,73.203 147.168,73.203 148.336,73.203 149.504,73.203 150.673,73.203 151.841,73.203 153.01,73.203 154.178,73.203 155.346,73.203 156.515,73.203 157.683,73.203 158.852,73.203 160.02,73.203 161.188,73.203 162.357,73.203 144.247,74.371 145.415,74.371 146.583,74.371 147.752,74.371 148.92,74.371 150.089,74.371 151.257,74.371 152.425,74.371 153.594,74.371 154.762,74.371 155.931,74.371 157.099,74.371 158.267,74.371 159.436,74.371 160.604,74.371 161.773,74.371 162.941,74.371 164.109,74.371 165.278,74.371 166.446,74.371 168.783,74.371 144.831,75.54 145.999,75.54 147.168,75.54 148.336,75.54 149.504,75.54 150.673,75.54 151.841,75.54 153.01,75.54 154.178,75.54 155.346,75.54 156.515,75.54 157.683,75.54 158.852,75.54 160.02,75.54 161.188,75.54 162.357,75.54 163.525,75.54 164.694,75.54 165.862,75.54 169.367,75.54 144.247,76.708 145.415,76.708 146.583,76.708 147.752,76.708 148.92,76.708 150.089,76.708 151.257,76.708 152.425,76.708 153.594,76.708 154.762,76.708 155.931,76.708 157.099,76.708 158.267,76.708 159.436,76.708 160.604,76.708 161.773,76.708 162.941,76.708 164.109,76.708 165.278,76.708 166.446,76.708 167.615,76.708 168.783,76.708 144.831,77.876 145.999,77.876 147.168,77.876 148.336,77.876 149.504,77.876 150.673,77.876 151.841,77.876 153.01,77.876 154.178,77.876 155.346,77.876 156.515,77.876 157.683,77.876 158.852,77.876 160.02,77.876 161.188,77.876 162.357,77.876 163.525,77.876 164.694,77.876 165.862,77.876 167.03,77.876 168.199,77.876 169.367,77.876 144.247,79.045 145.415,79.045 146.583,79.045 147.752,79.045 148.92,79.045 150.089,79.045 151.257,79.045 152.425,79.045 153.594,79.045 154.762,79.045 155.931,79.045 157.099,79.045 158.267,79.045 159.436,79.045 160.604,79.045 161.773,79.045 162.941,79.045 164.109,79.045 165.278,79.045 166.446,79.045 167.615,79.045 168.783,79.045
  other v3: 142.173,17.286 142.923,17.286 143.673,17.286 144.423,17.286 141.798,18.036 142.548,18.036 143.298,18.036 144.048,18.036 141.423,18.786 142.173,18.786 142.923,18.786 143.673,18.786 144.423,18.786 141.798,19.536 142.548,19.536 143.298,19.536 144.048,19.536 141.423,20.286 142.173,20.286 142.923,20.286 143.673,20.286 144.423,20.286 141.798,21.036 142.548,21.036 143.298,21.036 144.048,21.036 141.423,21.786 142.173,21.786 142.923,21.786 143.673,21.786 144.423,21.786 141.798,22.536 142.548,22.536 143.298,22.536 144.048,22.536 144.798,22.536 145.548,22.536 141.423,23.286 142.173,23.286 142.923,23.286 143.673,23.286 144.423,23.286 145.173,23.286 145.923,23.286 151.173,23.286 151.923,23.286 146.298,24.036 147.048,24.036 151.548,24.036 146.673,24.786 141.698,25.868 142.998,25.868 141.698,27.168 142.998,27.168 140.673,29.286 145.923,29.286 145.923,30.786 137.298,31.536 138.048,31.536 141.798,31.536 142.548,31.536 143.298,31.536 144.048,31.536 137.673,32.286 143.673,32.286 144.423,32.286 145.173,32.286 145.923,32.286 137.298,33.036 138.048,33.036 138.423,33.787 139.173,33.787 139.923,33.787 140.673,33.787 141.423,33.787 142.173,33.787 142.923,33.787 143.673,33.787 144.423,33.787 145.173,33.787 145.923,33.787 146.673,33.787 147.423,33.787
  other v5: 141.698,24.568 141.698,28.468 142.998,28.468
SW: C1.2 L1.1 U1.8 | length 4.1
  Top Layer w0.2: C1.2@137.623,24.577 139.612,24.577 U1.8@139.648,24.613
  Top Layer w1: C1.2@137.623,24.577 137.659,24.613 U1.8@139.648,24.613
VCC: C10.1 R2.2 U1.6 | length 14.9
  Top Layer w0.2: C10.1@137.426,27.949 C10.1@137.446,27.93
  Top Layer w0.3: v3(136.5,27.93) C10.1@137.446,27.93 138.223,27.153 U1.6@139.648,27.153 ; R2.2@145.085,30.397 v3(145.085,31.09)
  Bottom Layer w0.3: v3(136.5,27.93) 136.5,29.395 137.763,30.658 144.653,30.658 v3(145.085,31.09)
VDCBUS: C18.1 C20.1 D3.2 L2.2 R12.2 T1.5 U2.8 | length 197.9
  Top Layer w0.3: 48.951,16.947 49.606,17.602 53.986,17.602 61.316,24.932 61.316,60.122 v3(61.341,60.147) ; v3(73.088,72.59) U2.8@74.375,72.59
  Top Layer w1.5: C18.1@86.335,34.44 86.359,34.416 D3.2@89.623,34.416 ; T1.5@95.637,39.846 95.637,40.138 T1.5@95.733,40.234
  Top Layer w2: R12.2@44.571,16.947 48.951,16.947 49.24,16.947 52.861,13.326 53.211,13.326 53.561,13.326 57.083,9.804 70.684,9.804 C20.1@78.736,17.856 ; D3.2@89.891,34.391 89.804,34.391 89.725,34.312 89.725,31.864 78.835,20.974 78.835,17.955 C20.1@78.736,17.856 ; T1.5@95.809,40.315 95.809,33.096 81.069,18.356 79.236,18.356 C20.1@78.736,17.856
  Bottom Layer w0.3: v3(61.341,60.147) 61.341,65.913 68.018,72.59 v3(73.088,72.59)
  Bottom Layer w2: C20.1@78.736,17.856 79.236,18.356 95.733,34.853 T1.5@95.733,40.234
pads on no net: D6.2 T1.4 T1.6 T1.7 T1.10

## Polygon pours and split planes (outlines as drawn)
+24V on Bottom Layer "BOTTOM_LAYER_+24V_P106" (solid, remove dead copper, pour order 106): 129.057,58.139 131.576,60.554 166.802,60.554 166.802,27.765 158.883,27.698 145.173,41.027 145.173,44.227 129.057,44.217
SGND on Bottom Layer "BOTTOM_LAYER_SGND_P105" (solid, remove dead copper, pour order 105): 143.364,66.371 143.364,80.699 172.353,80.699 172.353,74.298 163.297,74.298 163.297,61.067 158.627,61.067 131.345,61.112 128.302,58.394 128.302,52.734 124.136,52.734 124.136,63.123 127.384,66.371
PGND on Bottom Layer "BOTTOM_LAYER_PGND_P102" (solid, remove dead copper, pour order 102): 77.025,81.737 85.217,81.737 85.217,77.165 84.303,76.251 80.645,76.251 77.025,76.251
NetQ1_3 on Bottom Layer "BOTTOM_LAYER_NETQ1_3_P096" (solid, remove dead copper, pour order 96): 65.43,43.772 65.804,44.145 76.855,44.145 77.281,43.719 77.281,41.097 65.938,41.097 65.43,41.529
PGND on Bottom Layer "BOTTOM_LAYER_PGND_P094" (solid, remove dead copper, pour order 94): 39.04,6.096 84.201,6.096 84.814,37.31 82.118,40.005 59.7,40.005 58.55,41.713 58.549,44.587 39.04,44.587
SGND on Bottom Layer "BOTTOM_LAYER_SGND_P092" (solid, remove dead copper, pour order 92): 149.936,19.875 150.978,18.834 150.978,4.915 152.273,3.619 167.818,3.619 172.39,8.192 172.39,74.803 162.763,74.803 162.815,61.121 167.48,60.995 167.48,26.215 155.415,26.211 155.385,22.314 147.168,22.314 146.634,21.78 146.304,21.78 146.304,20.099 146.286,20.081 146.491,19.875
SGND on Bottom Layer "BOTTOM_LAYER_SGND_P086" (solid, remove dead copper, pour order 86): 136.804,25.705 140.081,25.705 140.716,25.07 140.716,17.678 141.961,16.434 150.622,16.434 152.552,18.364 152.552,31.801 149.962,34.392 138.245,34.392 136.804,32.951
NetC12_1 on Bottom Layer "BOTTOM_LAYER_NETC12_1_P066" (solid, remove dead copper, pour order 66): 123.952,36.679 143.401,36.679 143.401,43.355 128.128,43.355 128.128,46.93 123.952,46.93
PGND on Bottom Layer "BOTTOM_LAYER_PGND_P062" (solid, remove dead copper, pour order 62): 39.206,83.541 39.152,44.12 58.496,44.12 58.496,83.541
PGND on Bottom Layer "BOTTOM_LAYER_PGND_P050" (solid, remove dead copper, pour order 50): 29.566,24.426 37.694,24.426 37.694,83.693 29.566,83.693
SGND on Top Layer "TOP_LAYER_SGND_P108" (solid, remove dead copper, pour order 108): 165.887,24.982 165.887,31.242 172.353,31.242 172.353,24.982
SGND on Top Layer "TOP_LAYER_SGND_P074" (solid, remove dead copper, pour order 74): 150.647,23.165 151.689,22.123 151.689,8.204 152.984,6.909 171.496,6.909 172.353,7.765 172.353,25.603 147.879,25.603 147.345,25.07 147.015,25.07 147.015,23.388 146.997,23.37 147.203,23.165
